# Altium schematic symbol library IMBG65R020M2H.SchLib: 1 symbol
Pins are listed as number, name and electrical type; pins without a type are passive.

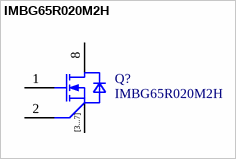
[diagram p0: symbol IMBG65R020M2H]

## IMBG65R020M2H
designator Q?
Insulated-Gate Field-Effect Transistor (IGFET), N-Channel, Enhancement, Body Diode, Pin 1 Gate, 2 Driver Source, 3 Power Source, 4 Power Source, 5 Power Source, 6 Power Source, 7 Power Source, 8 Drain, 8 Pins; Manufacturer: Infineon Technologies
pins: 1 GATE, 2 DRIVER SOURCE, 3 POWER SOURCE, 4 POWER SOURCE, 5 POWER SOURCE, 6 POWER SOURCE, 7 POWER SOURCE, 8 DRAIN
